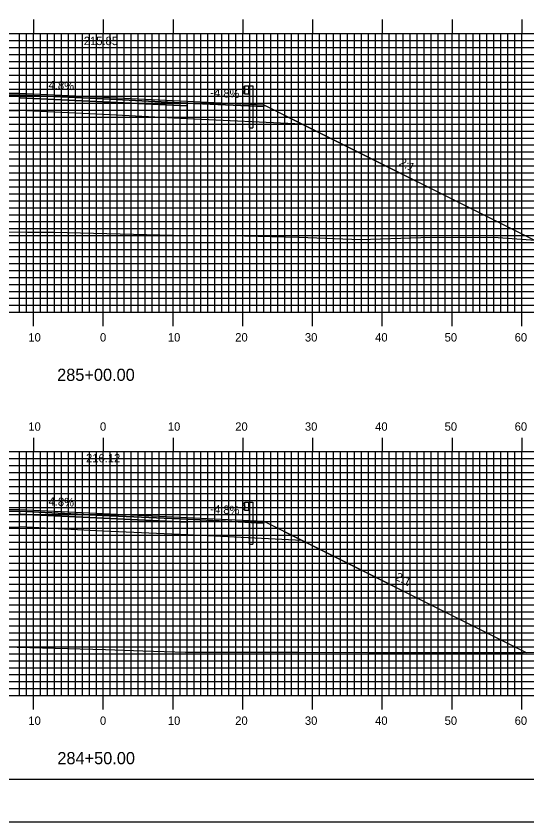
# Model space of a CAD drawing. Extents: x 1812161 to 1812504, y 442591 to 442811.
# Drawn here: x 1812313.9 to 1812387.2, y 442590.5 to 442706.2 of the extents above; entities that cross this region are included whole.
import ezdxf

# ---------------------------------------------------------------- set-up
doc = ezdxf.new("R2010")
doc.units = 0
for name, color, linetype in [('ANNOTATION', 7, 'Continuous'), ('BORDER', 7, 'Continuous'), ('D_Guardrail_Beam_Rt', 7, 'Continuous'), ('D_Roadway_Centerline', 7, 'Continuous'), ('D_Roadway_Centerline_Text', 7, 'Continuous'), ('D_Roadway_Edge_Shoulder', 7, 'Continuous'), ('D_Roadway_Edge_TW', 7, 'Continuous'), ('D_Roadway_Pavement', 7, 'Continuous'), ('D_Roadway_SlopeLines', 7, 'Continuous'), ('D_Roadway_SubGrade', 7, 'Continuous'), ('H_V ANNOTATION', 7, 'Continuous'), ('MAJOR', 7, 'Continuous'), ('MINOR', 7, 'Continuous'), ('PLOT BOUNDARY', 7, 'Continuous'), ('S_Roadway_Centerline', 7, 'Continuous')]:
    doc.layers.add(name, color=color, linetype=linetype)

msp = doc.modelspace()

# ---------------------------------------------------------------- linework, layer by layer
at = {"layer": 'BORDER'}
msp.add_lwpolyline([(1812176.83, 442596.67), (1812496.83, 442596.67), (1812496.83, 442806.67), (1812176.83, 442806.67)], close=True, dxfattribs=at)
at = {"layer": 'D_Guardrail_Beam_Rt'}
for p, q in [((1812346.61, 442696.04), (1812346.47, 442695.94)), ((1812346.7, 442696.06), (1812346.63, 442696.05)), ((1812346.7, 442696.14), (1812347.39, 442696.14)), ((1812346.7, 442694.98), (1812346.7, 442696.14)), ((1812347.22, 442696.14), (1812347.22, 442694.98)), ((1812347.32, 442696.14), (1812347.32, 442694.98)), ((1812347.39, 442696.14), (1812347.86, 442696.14)), ((1812347.39, 442696.14), (1812347.39, 442694.98)), ((1812347.86, 442696.14), (1812347.86, 442690.14)), ((1812346.47, 442695.8), (1812346.66, 442695.66)), ((1812346.66, 442695.46), (1812346.47, 442695.32)), ((1812346.47, 442695.18), (1812346.61, 442695.08)), ((1812346.63, 442695.07), (1812346.7, 442695.06)), ((1812346.7, 442695.6), (1812346.7, 442695.52)), ((1812347.39, 442694.98), (1812346.7, 442694.98)), ((1812347.37, 442690.14), (1812347.37, 442694.98)), ((1812347.37, 442690.14), (1812347.86, 442690.14)), ((1812346.61, 442636.3), (1812346.47, 442636.2)), ((1812346.47, 442636.06), (1812346.66, 442635.92)), ((1812346.7, 442636.32), (1812346.63, 442636.31)), ((1812346.7, 442636.41), (1812347.39, 442636.41)), ((1812346.7, 442635.24), (1812346.7, 442636.41)), ((1812346.7, 442635.86), (1812346.7, 442635.79)), ((1812347.22, 442636.41), (1812347.22, 442635.24)), ((1812347.32, 442636.41), (1812347.32, 442635.24)), ((1812347.39, 442636.41), (1812347.86, 442636.41)), ((1812347.39, 442636.41), (1812347.39, 442635.24)), ((1812347.86, 442636.41), (1812347.86, 442630.41)), ((1812346.66, 442635.72), (1812346.47, 442635.59)), ((1812346.47, 442635.44), (1812346.61, 442635.34)), ((1812346.63, 442635.34), (1812346.7, 442635.32)), ((1812347.39, 442635.24), (1812346.7, 442635.24)), ((1812347.37, 442630.41), (1812347.37, 442635.24)), ((1812347.37, 442630.41), (1812347.86, 442630.41))]:
    msp.add_line(p, q, dxfattribs=at)
for centre, major_axis, start_param, end_param in [((1812346.63, 442696), (-0.0417, 0), 4.907132, 5.323254), ((1812346.52, 442695.87), (-0.0877, 0), 5.323254, 7.243116), ((1812346.52, 442695.25), (-0.0877, 0), 5.323254, 7.243116), ((1812346.63, 442695.12), (-0.0417, 0), 0.959931, 1.376053), ((1812346.62, 442695.6), (0.0789, 0), 0, 0.959931), ((1812346.62, 442695.52), (0.0789, 0), 5.323254, 6.283185), ((1812346.52, 442636.13), (-0.0877, 0), 5.323254, 7.243116), ((1812346.63, 442636.27), (-0.0417, 0), 4.907132, 5.323254), ((1812346.62, 442635.86), (0.0789, 0), 0, 0.959931), ((1812346.52, 442635.52), (-0.0877, 0), 5.323254, 7.243116), ((1812346.63, 442635.38), (-0.0417, 0), 0.959931, 1.376053), ((1812346.62, 442635.79), (0.0789, 0), 5.323254, 6.283185)]:
    msp.add_ellipse(centre, major_axis=major_axis, ratio=0.995501, start_param=start_param, end_param=end_param, dxfattribs=at)
at = {"layer": 'D_Roadway_Centerline'}
for points in [[(1812264.46, 442675.39), (1812298.22, 442692.27), (1812303.43, 442694.88), (1812306.43, 442694.94), (1812314.43, 442695.1), (1812326.43, 442694.52), (1812338.43, 442693.94), (1812346.43, 442693.56), (1812349.43, 442693.42), (1812354.96, 442690.65), (1812388.17, 442674.04)], [(1812264.27, 442615.56), (1812298.22, 442632.53), (1812303.43, 442635.14), (1812306.43, 442635.2), (1812314.43, 442635.36), (1812326.43, 442634.78), (1812338.43, 442634.21), (1812346.43, 442633.82), (1812349.43, 442633.68), (1812354.96, 442630.91), (1812387.04, 442614.87)]]:
    msp.add_lwpolyline(points, dxfattribs=at)
at = {"layer": 'D_Roadway_Edge_Shoulder'}
for points in [[(1812314.43, 442695.1), (1812306.43, 442694.94), (1812306.43, 442694.94), (1812303.43, 442694.88), (1812303.43, 442694.63), (1812314.43, 442694.85)], [(1812338.43, 442693.94), (1812346.43, 442693.56), (1812346.43, 442693.56), (1812349.43, 442693.42), (1812349.43, 442693.17), (1812338.43, 442693.69)], [(1812314.43, 442635.36), (1812306.43, 442635.2), (1812306.43, 442635.2), (1812303.43, 442635.14), (1812303.43, 442634.89), (1812314.43, 442635.11)], [(1812338.43, 442634.21), (1812346.43, 442633.82), (1812346.43, 442633.82), (1812349.43, 442633.68), (1812349.43, 442633.43), (1812338.43, 442633.96)]]:
    msp.add_lwpolyline(points, close=True, dxfattribs=at)
at = {"layer": 'D_Roadway_Edge_TW'}
for points in [[(1812314.43, 442694.85), (1812314.43, 442695.1), (1812326.43, 442694.52), (1812338.43, 442693.94), (1812338.43, 442693.69), (1812326.43, 442694.27)], [(1812314.43, 442635.11), (1812314.43, 442635.36), (1812326.43, 442634.78), (1812338.43, 442634.21), (1812338.43, 442633.96), (1812326.43, 442634.53)]]:
    msp.add_lwpolyline(points, close=True, dxfattribs=at)
at = {"layer": 'D_Roadway_Pavement'}
for points in [[(1812314.43, 442694.43), (1812314.43, 442694.85), (1812326.43, 442694.27), (1812338.43, 442693.69), (1812338.43, 442693.28), (1812326.43, 442693.85)], [(1812314.43, 442634.69), (1812314.43, 442635.11), (1812326.43, 442634.53), (1812338.43, 442633.96), (1812338.43, 442633.54), (1812326.43, 442634.12)]]:
    msp.add_lwpolyline(points, close=True, dxfattribs=at)
for points in [[(1812314.43, 442694.85), (1812314.43, 442694.43)], [(1812338.43, 442693.69), (1812338.43, 442693.28)], [(1812314.43, 442635.11), (1812314.43, 442634.69)], [(1812338.43, 442633.96), (1812338.43, 442633.54)]]:
    msp.add_lwpolyline(points, dxfattribs=at)
at = {"layer": 'D_Roadway_SlopeLines'}
for points in [[(1812349.43, 442693.42), (1812388.17, 442674.04)], [(1812349.43, 442633.68), (1812387.04, 442614.87)]]:
    msp.add_lwpolyline(points, dxfattribs=at)
at = {"layer": 'D_Roadway_SubGrade'}
for points in [[(1812314.43, 442694.43), (1812314.43, 442694.85), (1812303.43, 442694.63), (1812303.43, 442694.88), (1812298.22, 442692.27), (1812314.43, 442692.6)], [(1812314.43, 442692.6), (1812314.43, 442694.85), (1812314.43, 442694.43), (1812326.43, 442693.85), (1812338.43, 442693.28), (1812338.43, 442693.69), (1812338.43, 442691.44), (1812326.43, 442692.02)], [(1812338.43, 442693.28), (1812338.43, 442693.69), (1812349.43, 442693.17), (1812349.43, 442693.42), (1812354.96, 442690.65), (1812338.43, 442691.44)], [(1812314.43, 442634.69), (1812314.43, 442635.11), (1812303.43, 442634.89), (1812303.43, 442635.14), (1812298.22, 442632.53), (1812314.43, 442632.86)], [(1812314.43, 442632.86), (1812314.43, 442635.11), (1812314.43, 442634.69), (1812326.43, 442634.12), (1812338.43, 442633.54), (1812338.43, 442633.96), (1812338.43, 442631.71), (1812326.43, 442632.28)], [(1812338.43, 442633.54), (1812338.43, 442633.96), (1812349.43, 442633.43), (1812349.43, 442633.68), (1812354.96, 442630.91), (1812338.43, 442631.71)]]:
    msp.add_lwpolyline(points, close=True, dxfattribs=at)
at = {"layer": 'MAJOR'}
for p, q in [((1812316.43, 442705.67), (1812316.43, 442703.67)), ((1812326.43, 442705.67), (1812326.43, 442703.67)), ((1812336.43, 442705.67), (1812336.43, 442703.67)), ((1812346.43, 442705.67), (1812346.43, 442703.67)), ((1812356.43, 442705.67), (1812356.43, 442703.67)), ((1812366.43, 442705.67), (1812366.43, 442703.67)), ((1812376.43, 442705.67), (1812376.43, 442703.67)), ((1812386.43, 442705.67), (1812386.43, 442703.67)), ((1812186.43, 442703.67), (1812466.43, 442703.67)), ((1812186.43, 442703.67), (1812466.43, 442703.67)), ((1812316.43, 442663.67), (1812316.43, 442703.67)), ((1812326.43, 442663.67), (1812326.43, 442703.67)), ((1812336.43, 442663.67), (1812336.43, 442703.67)), ((1812346.43, 442663.67), (1812346.43, 442703.67)), ((1812356.43, 442663.67), (1812356.43, 442703.67)), ((1812366.43, 442663.67), (1812366.43, 442703.67)), ((1812376.43, 442663.67), (1812376.43, 442703.67)), ((1812386.43, 442663.67), (1812386.43, 442703.67)), ((1812186.43, 442698.67), (1812466.43, 442698.67)), ((1812186.43, 442693.67), (1812466.43, 442693.67)), ((1812186.43, 442688.67), (1812466.43, 442688.67)), ((1812186.43, 442683.67), (1812466.43, 442683.67)), ((1812186.43, 442678.67), (1812466.43, 442678.67)), ((1812186.43, 442673.67), (1812466.43, 442673.67)), ((1812186.43, 442668.67), (1812466.43, 442668.67)), ((1812186.43, 442663.67), (1812466.43, 442663.67)), ((1812186.43, 442663.67), (1812466.43, 442663.67)), ((1812316.43, 442661.66), (1812316.43, 442663.67)), ((1812326.43, 442661.66), (1812326.43, 442663.67)), ((1812336.43, 442661.66), (1812336.43, 442663.67)), ((1812346.43, 442661.66), (1812346.43, 442663.67)), ((1812356.43, 442661.66), (1812356.43, 442663.67)), ((1812366.43, 442661.66), (1812366.43, 442663.67)), ((1812376.43, 442661.66), (1812376.43, 442663.67)), ((1812386.43, 442661.66), (1812386.43, 442663.67)), ((1812316.43, 442645.67), (1812316.43, 442643.67)), ((1812326.43, 442645.67), (1812326.43, 442643.67)), ((1812336.43, 442645.67), (1812336.43, 442643.67)), ((1812346.43, 442645.67), (1812346.43, 442643.67)), ((1812356.43, 442645.67), (1812356.43, 442643.67)), ((1812366.43, 442645.67), (1812366.43, 442643.67)), ((1812376.43, 442645.67), (1812376.43, 442643.67)), ((1812386.43, 442645.67), (1812386.43, 442643.67)), ((1812186.43, 442643.67), (1812466.43, 442643.67)), ((1812186.43, 442643.67), (1812466.43, 442643.67)), ((1812316.43, 442608.67), (1812316.43, 442643.67)), ((1812326.43, 442608.67), (1812326.43, 442643.67)), ((1812336.43, 442608.67), (1812336.43, 442643.67)), ((1812346.43, 442608.67), (1812346.43, 442643.67)), ((1812356.43, 442608.67), (1812356.43, 442643.67)), ((1812366.43, 442608.67), (1812366.43, 442643.67)), ((1812376.43, 442608.67), (1812376.43, 442643.67)), ((1812386.43, 442608.67), (1812386.43, 442643.67)), ((1812186.43, 442638.67), (1812466.43, 442638.67)), ((1812186.43, 442633.67), (1812466.43, 442633.67)), ((1812186.43, 442628.67), (1812466.43, 442628.67)), ((1812186.43, 442623.67), (1812466.43, 442623.67)), ((1812186.43, 442618.67), (1812466.43, 442618.67)), ((1812186.43, 442613.67), (1812466.43, 442613.67)), ((1812186.43, 442608.67), (1812466.43, 442608.67)), ((1812186.43, 442608.67), (1812466.43, 442608.67)), ((1812316.43, 442606.66), (1812316.43, 442608.67)), ((1812326.43, 442606.66), (1812326.43, 442608.67)), ((1812336.43, 442606.66), (1812336.43, 442608.67)), ((1812346.43, 442606.66), (1812346.43, 442608.67)), ((1812356.43, 442606.66), (1812356.43, 442608.67)), ((1812366.43, 442606.66), (1812366.43, 442608.67)), ((1812376.43, 442606.66), (1812376.43, 442608.67)), ((1812386.43, 442606.66), (1812386.43, 442608.67))]:
    msp.add_line(p, q, dxfattribs=at)
at = {"layer": 'MINOR'}
for p, q in [((1812314.43, 442663.67), (1812314.43, 442703.67)), ((1812315.43, 442663.67), (1812315.43, 442703.67)), ((1812317.43, 442663.67), (1812317.43, 442703.67)), ((1812318.43, 442663.67), (1812318.43, 442703.67)), ((1812319.43, 442663.67), (1812319.43, 442703.67)), ((1812320.43, 442663.67), (1812320.43, 442703.67)), ((1812321.43, 442663.67), (1812321.43, 442703.67)), ((1812322.43, 442663.67), (1812322.43, 442703.67)), ((1812323.43, 442663.67), (1812323.43, 442703.67)), ((1812324.43, 442663.67), (1812324.43, 442703.67)), ((1812325.43, 442663.67), (1812325.43, 442703.67)), ((1812327.43, 442663.67), (1812327.43, 442703.67)), ((1812328.43, 442663.67), (1812328.43, 442703.67)), ((1812329.43, 442663.67), (1812329.43, 442703.67)), ((1812330.43, 442663.67), (1812330.43, 442703.67)), ((1812331.43, 442663.67), (1812331.43, 442703.67)), ((1812332.43, 442663.67), (1812332.43, 442703.67)), ((1812333.43, 442663.67), (1812333.43, 442703.67)), ((1812334.43, 442663.67), (1812334.43, 442703.67)), ((1812335.43, 442663.67), (1812335.43, 442703.67)), ((1812337.43, 442663.67), (1812337.43, 442703.67)), ((1812338.43, 442663.67), (1812338.43, 442703.67)), ((1812339.43, 442663.67), (1812339.43, 442703.67)), ((1812340.43, 442663.67), (1812340.43, 442703.67)), ((1812341.43, 442663.67), (1812341.43, 442703.67)), ((1812342.43, 442663.67), (1812342.43, 442703.67)), ((1812343.43, 442663.67), (1812343.43, 442703.67)), ((1812344.43, 442663.67), (1812344.43, 442703.67)), ((1812345.43, 442663.67), (1812345.43, 442703.67)), ((1812347.43, 442663.67), (1812347.43, 442703.67)), ((1812348.43, 442663.67), (1812348.43, 442703.67)), ((1812349.43, 442663.67), (1812349.43, 442703.67)), ((1812350.43, 442663.67), (1812350.43, 442703.67)), ((1812351.43, 442663.67), (1812351.43, 442703.67)), ((1812352.43, 442663.67), (1812352.43, 442703.67)), ((1812353.43, 442663.67), (1812353.43, 442703.67)), ((1812354.43, 442663.67), (1812354.43, 442703.67)), ((1812355.43, 442663.67), (1812355.43, 442703.67)), ((1812357.43, 442663.67), (1812357.43, 442703.67)), ((1812358.43, 442663.67), (1812358.43, 442703.67)), ((1812359.43, 442663.67), (1812359.43, 442703.67)), ((1812360.43, 442663.67), (1812360.43, 442703.67)), ((1812361.43, 442663.67), (1812361.43, 442703.67)), ((1812362.43, 442663.67), (1812362.43, 442703.67)), ((1812363.43, 442663.67), (1812363.43, 442703.67)), ((1812364.43, 442663.67), (1812364.43, 442703.67)), ((1812365.43, 442663.67), (1812365.43, 442703.67)), ((1812367.43, 442663.67), (1812367.43, 442703.67)), ((1812368.43, 442663.67), (1812368.43, 442703.67)), ((1812369.43, 442663.67), (1812369.43, 442703.67)), ((1812370.43, 442663.67), (1812370.43, 442703.67)), ((1812371.43, 442663.67), (1812371.43, 442703.67)), ((1812372.43, 442663.67), (1812372.43, 442703.67)), ((1812373.43, 442663.67), (1812373.43, 442703.67)), ((1812374.43, 442663.67), (1812374.43, 442703.67)), ((1812375.43, 442663.67), (1812375.43, 442703.67)), ((1812377.43, 442663.67), (1812377.43, 442703.67)), ((1812378.43, 442663.67), (1812378.43, 442703.67)), ((1812379.43, 442663.67), (1812379.43, 442703.67)), ((1812380.43, 442663.67), (1812380.43, 442703.67)), ((1812381.43, 442663.67), (1812381.43, 442703.67)), ((1812382.43, 442663.67), (1812382.43, 442703.67)), ((1812383.43, 442663.67), (1812383.43, 442703.67)), ((1812384.43, 442663.67), (1812384.43, 442703.67)), ((1812385.43, 442663.67), (1812385.43, 442703.67)), ((1812186.43, 442702.67), (1812466.43, 442702.67)), ((1812186.43, 442701.67), (1812466.43, 442701.67)), ((1812186.43, 442700.67), (1812466.43, 442700.67)), ((1812186.43, 442699.67), (1812466.43, 442699.67)), ((1812186.43, 442697.67), (1812466.43, 442697.67)), ((1812186.43, 442696.67), (1812466.43, 442696.67)), ((1812186.43, 442695.67), (1812466.43, 442695.67)), ((1812186.43, 442694.67), (1812466.43, 442694.67)), ((1812186.43, 442692.67), (1812466.43, 442692.67)), ((1812186.43, 442691.67), (1812466.43, 442691.67)), ((1812186.43, 442690.67), (1812466.43, 442690.67)), ((1812186.43, 442689.67), (1812466.43, 442689.67)), ((1812186.43, 442687.67), (1812466.43, 442687.67)), ((1812186.43, 442686.67), (1812466.43, 442686.67)), ((1812186.43, 442685.67), (1812466.43, 442685.67)), ((1812186.43, 442684.67), (1812466.43, 442684.67)), ((1812186.43, 442682.67), (1812466.43, 442682.67)), ((1812186.43, 442681.67), (1812466.43, 442681.67)), ((1812186.43, 442680.67), (1812466.43, 442680.67)), ((1812186.43, 442679.67), (1812466.43, 442679.67)), ((1812186.43, 442677.67), (1812466.43, 442677.67)), ((1812186.43, 442676.67), (1812466.43, 442676.67)), ((1812186.43, 442675.67), (1812466.43, 442675.67)), ((1812186.43, 442674.67), (1812466.43, 442674.67)), ((1812186.43, 442672.67), (1812466.43, 442672.67)), ((1812186.43, 442671.67), (1812466.43, 442671.67)), ((1812186.43, 442670.67), (1812466.43, 442670.67)), ((1812186.43, 442669.67), (1812466.43, 442669.67)), ((1812186.43, 442667.67), (1812466.43, 442667.67)), ((1812186.43, 442666.67), (1812466.43, 442666.67)), ((1812186.43, 442665.67), (1812466.43, 442665.67)), ((1812186.43, 442664.67), (1812466.43, 442664.67)), ((1812314.43, 442608.67), (1812314.43, 442643.67)), ((1812315.43, 442608.67), (1812315.43, 442643.67)), ((1812317.43, 442608.67), (1812317.43, 442643.67)), ((1812318.43, 442608.67), (1812318.43, 442643.67)), ((1812319.43, 442608.67), (1812319.43, 442643.67)), ((1812320.43, 442608.67), (1812320.43, 442643.67)), ((1812321.43, 442608.67), (1812321.43, 442643.67)), ((1812322.43, 442608.67), (1812322.43, 442643.67)), ((1812323.43, 442608.67), (1812323.43, 442643.67)), ((1812324.43, 442608.67), (1812324.43, 442643.67)), ((1812325.43, 442608.67), (1812325.43, 442643.67)), ((1812327.43, 442608.67), (1812327.43, 442643.67)), ((1812328.43, 442608.67), (1812328.43, 442643.67)), ((1812329.43, 442608.67), (1812329.43, 442643.67)), ((1812330.43, 442608.67), (1812330.43, 442643.67)), ((1812331.43, 442608.67), (1812331.43, 442643.67)), ((1812332.43, 442608.67), (1812332.43, 442643.67)), ((1812333.43, 442608.67), (1812333.43, 442643.67)), ((1812334.43, 442608.67), (1812334.43, 442643.67)), ((1812335.43, 442608.67), (1812335.43, 442643.67)), ((1812337.43, 442608.67), (1812337.43, 442643.67)), ((1812338.43, 442608.67), (1812338.43, 442643.67)), ((1812339.43, 442608.67), (1812339.43, 442643.67)), ((1812340.43, 442608.67), (1812340.43, 442643.67)), ((1812341.43, 442608.67), (1812341.43, 442643.67)), ((1812342.43, 442608.67), (1812342.43, 442643.67)), ((1812343.43, 442608.67), (1812343.43, 442643.67)), ((1812344.43, 442608.67), (1812344.43, 442643.67)), ((1812345.43, 442608.67), (1812345.43, 442643.67)), ((1812347.43, 442608.67), (1812347.43, 442643.67)), ((1812348.43, 442608.67), (1812348.43, 442643.67)), ((1812349.43, 442608.67), (1812349.43, 442643.67)), ((1812350.43, 442608.67), (1812350.43, 442643.67)), ((1812351.43, 442608.67), (1812351.43, 442643.67)), ((1812352.43, 442608.67), (1812352.43, 442643.67)), ((1812353.43, 442608.67), (1812353.43, 442643.67)), ((1812354.43, 442608.67), (1812354.43, 442643.67)), ((1812355.43, 442608.67), (1812355.43, 442643.67)), ((1812357.43, 442608.67), (1812357.43, 442643.67)), ((1812358.43, 442608.67), (1812358.43, 442643.67)), ((1812359.43, 442608.67), (1812359.43, 442643.67)), ((1812360.43, 442608.67), (1812360.43, 442643.67)), ((1812361.43, 442608.67), (1812361.43, 442643.67)), ((1812362.43, 442608.67), (1812362.43, 442643.67)), ((1812363.43, 442608.67), (1812363.43, 442643.67)), ((1812364.43, 442608.67), (1812364.43, 442643.67)), ((1812365.43, 442608.67), (1812365.43, 442643.67)), ((1812367.43, 442608.67), (1812367.43, 442643.67)), ((1812368.43, 442608.67), (1812368.43, 442643.67)), ((1812369.43, 442608.67), (1812369.43, 442643.67)), ((1812370.43, 442608.67), (1812370.43, 442643.67)), ((1812371.43, 442608.67), (1812371.43, 442643.67)), ((1812372.43, 442608.67), (1812372.43, 442643.67)), ((1812373.43, 442608.67), (1812373.43, 442643.67)), ((1812374.43, 442608.67), (1812374.43, 442643.67)), ((1812375.43, 442608.67), (1812375.43, 442643.67)), ((1812377.43, 442608.67), (1812377.43, 442643.67)), ((1812378.43, 442608.67), (1812378.43, 442643.67)), ((1812379.43, 442608.67), (1812379.43, 442643.67)), ((1812380.43, 442608.67), (1812380.43, 442643.67)), ((1812381.43, 442608.67), (1812381.43, 442643.67)), ((1812382.43, 442608.67), (1812382.43, 442643.67)), ((1812383.43, 442608.67), (1812383.43, 442643.67)), ((1812384.43, 442608.67), (1812384.43, 442643.67)), ((1812385.43, 442608.67), (1812385.43, 442643.67)), ((1812186.43, 442642.67), (1812466.43, 442642.67)), ((1812186.43, 442641.67), (1812466.43, 442641.67)), ((1812186.43, 442640.67), (1812466.43, 442640.67)), ((1812186.43, 442639.67), (1812466.43, 442639.67)), ((1812186.43, 442637.67), (1812466.43, 442637.67)), ((1812186.43, 442636.67), (1812466.43, 442636.67)), ((1812186.43, 442635.67), (1812466.43, 442635.67)), ((1812186.43, 442634.67), (1812466.43, 442634.67)), ((1812186.43, 442632.67), (1812466.43, 442632.67)), ((1812186.43, 442631.67), (1812466.43, 442631.67)), ((1812186.43, 442630.67), (1812466.43, 442630.67)), ((1812186.43, 442629.67), (1812466.43, 442629.67)), ((1812186.43, 442627.67), (1812466.43, 442627.67)), ((1812186.43, 442626.67), (1812466.43, 442626.67)), ((1812186.43, 442625.67), (1812466.43, 442625.67)), ((1812186.43, 442624.67), (1812466.43, 442624.67)), ((1812186.43, 442622.67), (1812466.43, 442622.67)), ((1812186.43, 442621.67), (1812466.43, 442621.67)), ((1812186.43, 442620.67), (1812466.43, 442620.67)), ((1812186.43, 442619.67), (1812466.43, 442619.67)), ((1812186.43, 442617.67), (1812466.43, 442617.67)), ((1812186.43, 442616.67), (1812466.43, 442616.67)), ((1812186.43, 442615.67), (1812466.43, 442615.67)), ((1812186.43, 442614.67), (1812466.43, 442614.67)), ((1812186.43, 442612.67), (1812466.43, 442612.67)), ((1812186.43, 442611.67), (1812466.43, 442611.67)), ((1812186.43, 442610.67), (1812466.43, 442610.67)), ((1812186.43, 442609.67), (1812466.43, 442609.67))]:
    msp.add_line(p, q, dxfattribs=at)
at = {"layer": 'PLOT BOUNDARY'}
msp.add_lwpolyline([(1812160.64, 442590.55), (1812500.64, 442590.55), (1812500.64, 442810.55), (1812160.64, 442810.55)], close=True, dxfattribs=at)
at = {"layer": 'S_Roadway_Centerline'}
for points in [[(1812186.43, 442674.96), (1812193.49, 442674.87), (1812194.41, 442674.88), (1812195.23, 442674.88), (1812210.71, 442676.18), (1812219.13, 442675.79), (1812230.64, 442676.24), (1812243.89, 442676.54), (1812246.7, 442676.6), (1812257.26, 442675.86), (1812265.07, 442675.35), (1812269.05, 442675.38), (1812278.98, 442675.22), (1812294.55, 442675.24), (1812315.55, 442675.14), (1812318.24, 442675.16), (1812319.32, 442675.14), (1812336.42, 442674.72), (1812344.7, 442674.69), (1812354.49, 442674.44), (1812363.29, 442674.11), (1812371.95, 442674.39), (1812382.38, 442674.43), (1812389.75, 442673.94)], [(1812248.45, 442615.83), (1812261.63, 442615.57), (1812274.45, 442615.53), (1812276.55, 442615.54), (1812280.86, 442615.61), (1812296.38, 442615.39), (1812302.51, 442615.82), (1812314.06, 442615.61), (1812326.73, 442615.27), (1812332.08, 442615.07), (1812338.22, 442614.92), (1812354.27, 442614.92), (1812364.46, 442614.86), (1812368.1, 442614.86), (1812377.02, 442614.84), (1812386.61, 442614.87), (1812389.66, 442614.89)]]:
    msp.add_lwpolyline(points, dxfattribs=at)

# ---------------------------------------------------------------- texts
at = {"layer": 'ANNOTATION'}
for s, rotation, p in [('4.8%', 357.2519, (1812318.56, 442695.7)), ('-4.8%', 357.2519, (1812341.74, 442694.59)), ('2:1', 333.4349, (1812368.73, 442684.8)), ('4.8%', 357.2519, (1812318.56, 442635.96)), ('-4.8%', 357.2519, (1812341.74, 442634.85)), ('2:1', 333.4349, (1812368.17, 442625.34))]:
    msp.add_text(s, height=1.2, rotation=rotation, dxfattribs=at).set_placement(p)
at = {"layer": 'D_Roadway_Centerline'}
for s, p in [('C', (1812326.42, 442694.52)), ('L', (1812326.43, 442694.51)), ('C', (1812326.42, 442634.78)), ('L', (1812326.43, 442634.78))]:
    msp.add_text(s, height=0.0146, dxfattribs=at).set_placement(p)
at = {"layer": 'D_Roadway_Centerline_Text'}
for s, p in [('215.85', (1812323.63, 442702)), ('216.12', (1812323.95, 442642.14))]:
    msp.add_text(s, height=1.2, dxfattribs=at).set_placement(p)
at = {"layer": 'H_V ANNOTATION'}
for s, height, p in [('10', 1.2, (1812315.68, 442659.47)), ('0', 1.2, (1812325.95, 442659.47)), ('10', 1.2, (1812335.68, 442659.47)), ('20', 1.2, (1812345.34, 442659.47)), ('30', 1.2, (1812355.33, 442659.47)), ('40', 1.2, (1812365.4, 442659.47)), ('50', 1.2, (1812375.36, 442659.47)), ('60', 1.2, (1812385.4, 442659.47)), ('285+00.00', 1.75, (1812319.81, 442653.82)), ('10', 1.2, (1812315.68, 442646.67)), ('0', 1.2, (1812325.95, 442646.67)), ('10', 1.2, (1812335.68, 442646.67)), ('20', 1.2, (1812345.34, 442646.67)), ('30', 1.2, (1812355.33, 442646.67)), ('40', 1.2, (1812365.4, 442646.67)), ('50', 1.2, (1812375.36, 442646.67)), ('60', 1.2, (1812385.4, 442646.67)), ('10', 1.2, (1812315.68, 442604.47)), ('0', 1.2, (1812325.95, 442604.47)), ('10', 1.2, (1812335.68, 442604.47)), ('20', 1.2, (1812345.34, 442604.47)), ('30', 1.2, (1812355.33, 442604.47)), ('40', 1.2, (1812365.4, 442604.47)), ('50', 1.2, (1812375.36, 442604.47)), ('60', 1.2, (1812385.4, 442604.47)), ('284+50.00', 1.75, (1812319.84, 442598.82))]:
    msp.add_text(s, height=height, dxfattribs=at).set_placement(p)

doc.saveas('drawing.dxf')
